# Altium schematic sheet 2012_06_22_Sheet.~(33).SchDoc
size A4
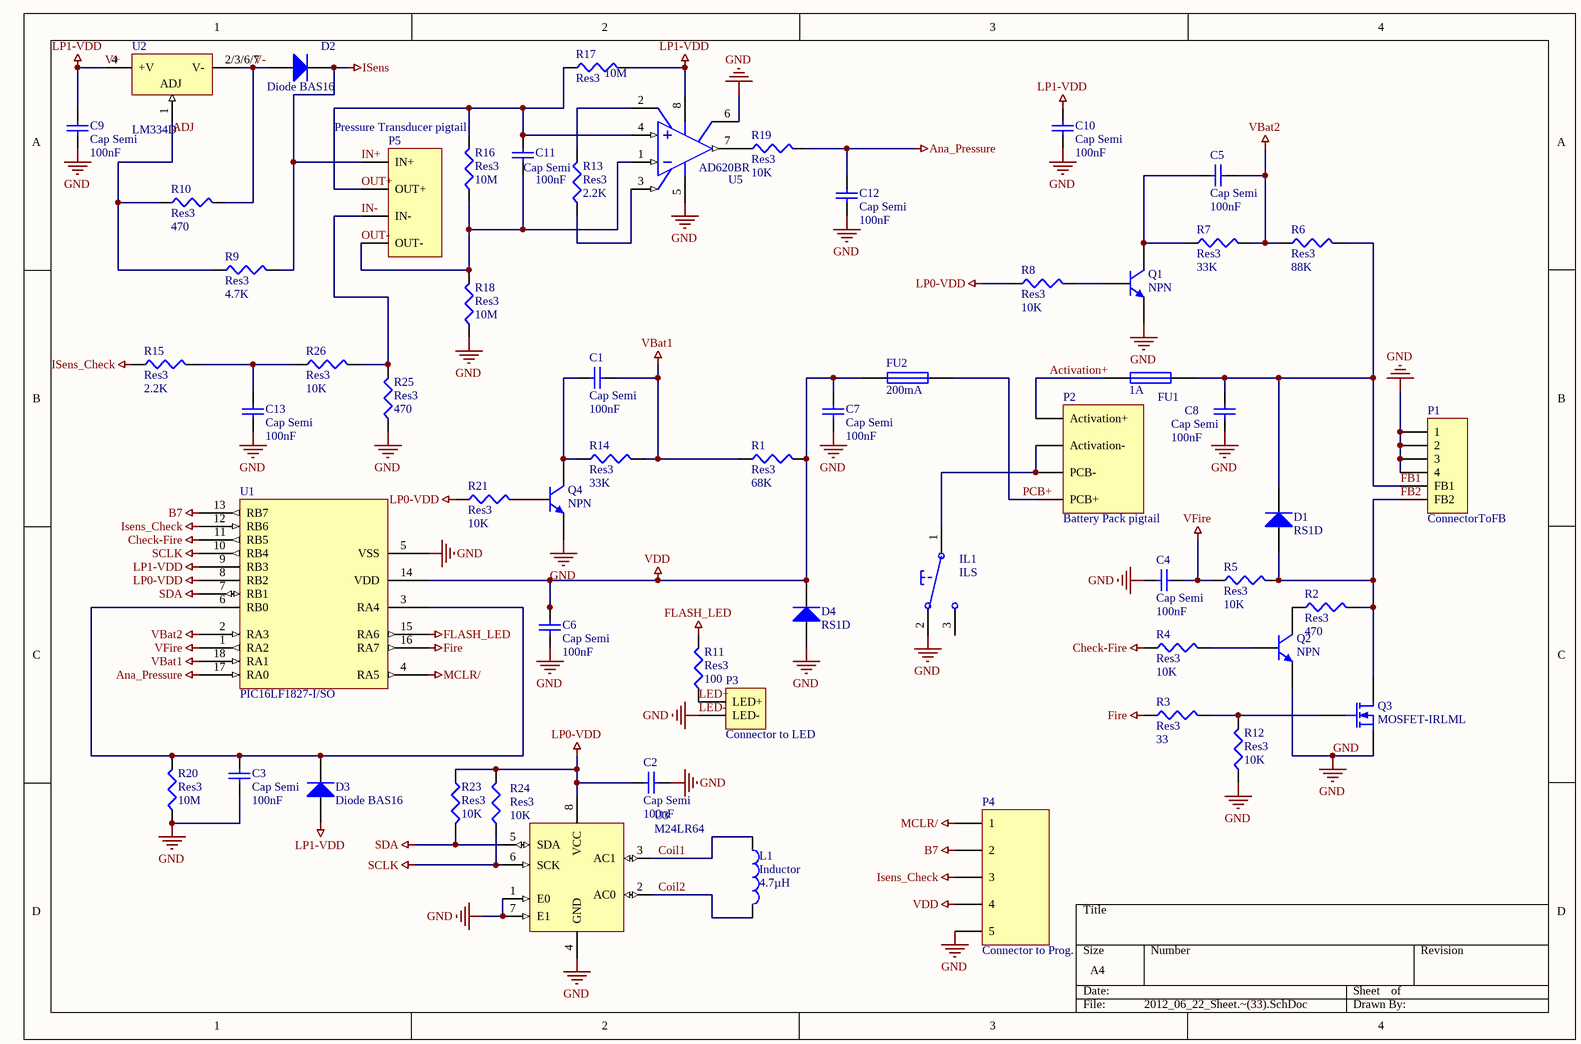
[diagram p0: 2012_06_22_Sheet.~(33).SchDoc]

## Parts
C1  Cap Semi  value 100nF  [1608[0603]]
C2  Cap Semi  value 100nF  [1608[0603]]
C3  Cap Semi  value 100nF  [1608[0603]]
C4  Cap Semi  value 100nF  [1608[0603]]
C5  Cap Semi  value 100nF  [1608[0603]]
C6  Cap Semi  value 100nF  [1608[0603]]
C7  Cap Semi  value 100nF  [1608[0603]]
C8  Cap Semi  value 100nF  [1608[0603]]
C9  Cap Semi  value 100nF  [1608[0603]]
C10  Cap Semi  value 100nF  [1608[0603]]
C11  Cap Semi  value 100nF  [1608[0603]]
C12  Cap Semi  value 100nF  [1608[0603]]
C13  Cap Semi  value 100nF  [1608[0603]]
D1  RS1D  [DiodeRS1D(recommendedfootprint)]
D2  Diode BAS16  [SOT-23_M]
D3  Diode BAS16  [SOT-23_M]
D4  RS1D  [DiodeRS1D(recommendedfootprint)]
FU1  1A  [FU(recommendedfootprint)]
FU2  200mA  [FU(recommendedfootprint)]
IL1  ILS  [ILS]
L1  Inductor  value 4.7µH  [INDC4532]
P1  ConnectorToFB  [HIROSE DF3A-6P]
P2  Battery Pack pigtail  [HDR1X4]
P3  Connector to LED  [HDR1X2]
P4  Connector to Prog.  [HDR1X5]
P5  Pressure Transducer pigtail  [HDR1X4]
Q1  NPN  [transistor_SOT-23(recommendedfootprint)]
Q2  NPN  [transistor_SOT-23(recommendedfootprint)]
Q3  MOSFET-IRLML  [transistor_SOT-23(recommendedfootprint)]
Q4  NPN  [transistor_SOT-23(recommendedfootprint)]
R1  Res3  value 68K  [J1-0603]
R2  Res3  value 470  [J1-0603]
R3  Res3  value 33  [J1-0603]
R4  Res3  value 10K  [J1-0603]
R5  Res3  value 10K  [J1-0603]
R6  Res3  value 88K  [J1-0603]
R7  Res3  value 33K  [J1-0603]
R8  Res3  value 10K  [J1-0603]
R9  Res3  value 4.7K  [J1-0603]
R10  Res3  value 470  [J1-0603]
R11  Res3  value 100  [J1-0603]
R12  Res3  value 10K  [J1-0603]
R13  Res3  value 2.2K  [J1-0603]
R14  Res3  value 33K  [J1-0603]
R15  Res3  value 2.2K  [J1-0603]
R16  Res3  value 10M  [J1-0603]
R17  Res3  value 10M  [J1-0603]
R18  Res3  value 10M  [1608[0603]]
R19  Res3  value 10K  [J1-0603]
R20  Res3  value 10M  [J1-0603]
R21  Res3  value 10K  [J1-0603]
R23  Res3  value 10K  [J1-0603]
R24  Res3  value 10K  [J1-0603]
R25  Res3  value 470  [J1-0603]
R26  Res3  value 10K  [J1-0603]
U1  PIC16LF1827-I/SO  [SOIC-SO18_L]
U2  LM334D  [SO8_N]
U3  M24LR64  [SO8N_N]
U5  AD620BR  [R-8D_N]

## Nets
Ana_Pressure: C12.2 R19.2 U1.17(RA0)
B7: P4.2 U1.13(RB7)
Check-Fire: R4.1 U1.11(RB5)
Fire: R3.1 U1.16(RA7)
FLASH_LED: R11.2 U1.15(RA6)
GND: C2.1 C3.1 C4.1 C6.1 C7.1 C8.1 C9.1 C10.1 C12.1 C13.1 D4.1(A) IL1.2 P1.1 P1.2 P1.3 P1.4 P3.2(LED-) P4.5 Q1.3(E) Q2.3(E) Q3.3(S) Q4.3(E) R12.1 R18.1 R20.1 R25.1 U1.5(VSS) U3.1(E0) U3.4(GND) U3.7(E1) U5.5(V-) U5.6(RG)  [also labelled LED-]
IN+: D2.3(K) P5.1(IN+) R9.2  [also labelled ISens]
Isens_Check: P4.3 R15.1 U1.12(RB6)
LP0-VDD: C2.2 R8.1 R21.1 R23.1 R24.2 U1.8(RB2) U3.8(VCC)
MCLR/: P4.1 U1.4(RA5)
SCLK: R24.1 U1.10(RB4) U3.6(SCK)
SDA: R23.2 U1.7(RB1) U3.5(SDA)
V+: C9.2 C10.2 D3.1(A) R17.2 U1.9(RB3) U2.4(+V) U5.8(V+)  [also labelled LP1-VDD]
VBat1: C1.2 R1.1 R14.2 U1.18(RA1)
VBat2: C5.2 R6.1 R7.2 U1.2(RA3)
VDD: C6.2 C7.2 D4.2(K) FU2.1 P4.4 R1.2 U1.14(VDD)
VFire: C4.2 R5.1 U1.1(RA2)
Activation+: FU1.1 P2.1(Activation+)
ADJ: R9.1 R10.1 U2.1(ADJ)
Coil1: L1.1 U3.3(AC1)
Coil2: L1.2 U3.2(AC0)
FB1: C8.2 D1.2(K) FU1.2 P1.6(FB1) R6.2
FB2: D1.1(A) P1.5(FB2) Q3.1(D) R2.2 R5.2
IN-: P5.3(IN-) R25.2 R26.2
LED+: P3.1(LED+) R11.1
OUT+: C11.2 P5.2(OUT+) R16.2 R17.1 U5.4(+IN)
OUT-: C11.1 P5.4(OUT-) R16.1 R18.2 U5.1(-IN)
PCB+: FU2.2 P2.4(PCB+)
V-: D2.1(A) R10.2 U2.2/3/6/7(V-)
NetC1_1: C1.1 Q4.1(C) R14.1
NetC3_2: C3.2 D3.3(K) R20.2 U1.3(RA4) U1.6(RB0)
NetC5_1: C5.1 Q1.1(C) R7.1
NetC13_2: C13.2 R15.2 R26.1
NetIL1_1: IL1.1 P2.2(Activation-) P2.3(PCB-)
NetQ1_2: Q1.2(B) R8.2
NetQ2_1: Q2.1(C) R2.1
NetQ2_2: Q2.2(B) R4.2
NetQ3_2: Q3.2(G) R3.2 R12.2
NetQ4_2: Q4.2(B) R21.2
NetR13_1: R13.1 U5.3(REF)
NetR13_2: R13.2 U5.2(RG)
NetR19_1: R19.1 U5.7(OUT)

Not connected (* = marked no-connect by the designer): IL1 3

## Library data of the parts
C1-C13 = Cap Semi: Capacitor (Semiconductor SIM Model)
D1 D4 = Diode: Default Diode
D2 D3 = Diode BAS16: Silicon Switching Diode for High-Speed Switching; Note: Pin 2 is not connected and not drawn.
FU1 FU2 = Fuse 1: Fuse
IL1 = ILS: SPDT Subminiature Toggle Switch, Right Angle Mounting, Vertical Actuation
L1 = Inductor: Code_IEC: 1005
P1 = ConnectorToFB: Header, 6-Pin
P2 = Battery Pack pigtail: Header, 4-Pin
P3 = Connector to LED: Header, 2-Pin
P4 = Connector to Prog.: Header, 5-Pin
P5 = Pressure Transducer pigtail: Header, 4-Pin
Q1 Q2 Q4 = NPN: NPN Bipolar Transistor
Q3 = MOSFET-IRLML: N-Channel MOSFET
R1-R21 R23-R26 = Res3: Resistor
U1 = PIC16LF1827-I/SO: EPROM-Based 8-Bit CMOS Microcontroller, 25 Bytes RAM, 4 MHz, 18-Pin SOIC, 3.0 to 5.5V Supply Range, Extended Temperature; Note: Verify oscillator characteristics if changing from this device to another.; Note: 20mA source and 25mA sink per I/O.
U2 = LM334D: Three Terminal Adjustable Current Source
U3 = M24LR64: 32 Kbit Serial I²C Bus EEPROM
U5 = AD620BR: Low-Cost, Low-Power Instrumentation Amplifier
